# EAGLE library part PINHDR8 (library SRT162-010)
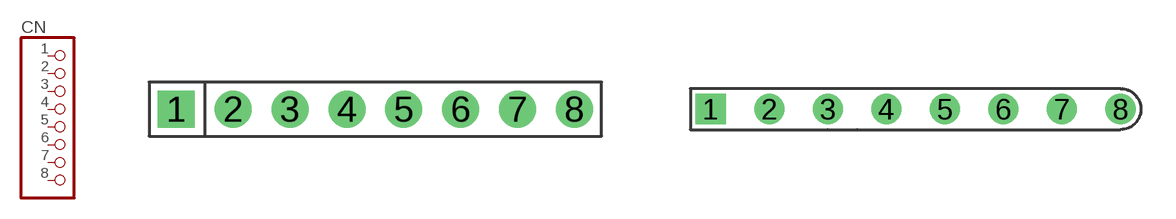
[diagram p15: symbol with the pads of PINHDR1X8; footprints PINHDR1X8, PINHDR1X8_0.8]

Designator prefix CN

## PINHDR8  [PINHDR1X8]
1  1  pas
2  2  pas
3  3  pas
4  4  pas
5  5  pas
6  6  pas
7  7  pas
8  8  pas

## PINHDR80.8  [PINHDR1X8_0.8]
Pads as for PINHDR1X8

## PINHDR81.0  [PINHDR1X8_1.0]
Pads as for PINHDR1X8

## Footprint PINHDR1X8 (pad centres in mm)
drill 1.1 square: 1 -8.89,0
drill 1.1 round: 2 -6.35,0; 3 -3.81,0; 4 -1.27,0; 5 1.27,0; 6 3.81,0; 7 6.35,0; 8 8.89,0

## Footprint PINHDR1X8_0.8 (pad centres in mm)
drill 0.8 square: 1 -8.89,0
drill 0.8 round: 2 -6.35,0; 3 -3.81,0; 4 -1.27,0; 5 1.27,0; 6 3.81,0; 7 6.35,0; 8 8.89,0

## Footprint PINHDR1X8_1.0 (pad centres in mm)
drill 1 square: 1 -8.89,0
drill 1 round: 2 -6.35,0; 3 -3.81,0; 4 -1.27,0; 5 1.27,0; 6 3.81,0; 7 6.35,0; 8 8.89,0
